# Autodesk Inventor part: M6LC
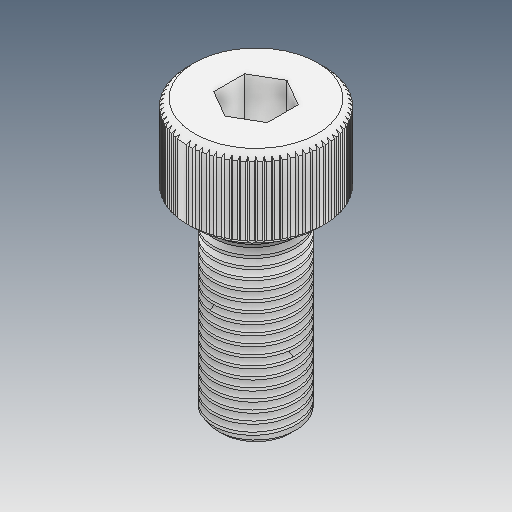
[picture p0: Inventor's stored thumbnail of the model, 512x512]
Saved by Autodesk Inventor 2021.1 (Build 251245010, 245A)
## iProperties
Created: 2021-05
Part Number: M6LC
Material: Ogólny
Document SubType Name: Modeling
Designer: user
Density: 1 g/cm^3
Appearance: Domyślna
Author: user
Revision Number: ÈÎºÎ
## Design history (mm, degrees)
feature "ÊäÈë1"
node "Bryła1"
